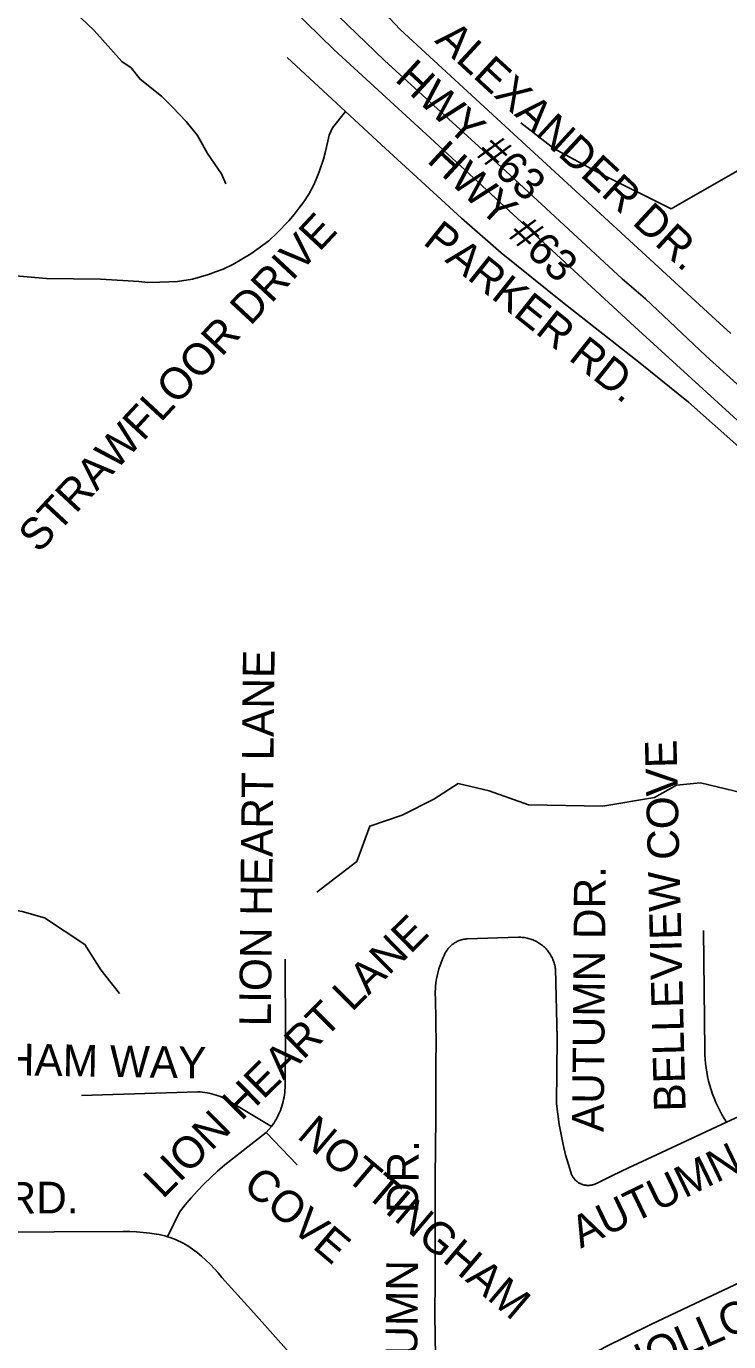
# Model space of a CAD drawing. Extents: x 1670563 to 1761545, y 515755 to 578944.
# Drawn here: x 1683746 to 1685409, y 542857 to 545971 of the extents above; entities that cross this region are included whole.
import ezdxf

# ---------------------------------------------------------------- set-up
doc = ezdxf.new("R2010")
doc.units = 0
for name, color, linetype in [('SHP_LINE', 7, 'Continuous'), ('STREETCL', 7, 'Continuous'), ('STRNAMES', 7, 'Continuous')]:
    doc.layers.add(name, color=color, linetype=linetype)

msp = doc.modelspace()

# ---------------------------------------------------------------- linework, layer by layer
at = {"layer": 'SHP_LINE'}
for points in [[(1683533, 546411), (1683633, 546396), (1683691, 546360), (1683739, 546315), (1683766, 546275), (1683782, 546206), (1683779, 546151), (1683794, 546106), (1683848, 546033), (1683875, 545991), (1683906, 545961), (1683972, 545888), (1683994, 545873), (1684015, 545846), (1684066, 545806), (1684093, 545779), (1684124, 545746), (1684151, 545713), (1684175, 545670), (1684208, 545622), (1684218, 545598)], [(1684917, 545743), (1684995, 545682), (1685100, 545625), (1685273, 545539)], [(1685799, 545725), (1685678, 545744), (1685563, 545715), (1685490, 545659), (1685431, 545630), (1685319, 545566), (1685273, 545539)], [(1684434, 543921), (1684528, 543994), (1684559, 544077), (1684636, 544103), (1684711, 544141), (1684768, 544178), (1684842, 544161), (1684935, 544128), (1685111, 544125), (1685233, 544145), (1685285, 544174), (1685342, 544180), (1685441, 544156), (1685585, 544093), (1685651, 544060), (1685728, 544033), (1685863, 544018), (1686108, 544018), (1686204, 544030), (1686304, 544039)], [(1683461, 543916), (1683562, 543899), (1683630, 543891), (1683686, 543884), (1683736, 543875), (1683789, 543860), (1683884, 543797), (1683922, 543737), (1683966, 543681)]]:
    msp.add_lwpolyline(points, dxfattribs=at)
at = {"layer": 'STREETCL'}
for points in [[(1685913, 544593.8), (1685635.2, 544850.4), (1685187, 545259.7), (1684701.8, 545707), (1684475, 545915.1), (1684373.9, 546014.5), (1684262.2, 546130.7), (1684078.4, 546335.4), (1683914.6, 546534.9), (1683762.8, 546737.1), (1683648.3, 546903.8)], [(1686352, 544277.5), (1686274.8, 544347.4), (1686127.6, 544481.9), (1685917.7, 544676.6), (1685823.7, 544763.5), (1685559.2, 545005.9), (1685354.8, 545191.1), (1685211.5, 545325.6), (1685156.9, 545373.2), (1684870.9, 545637.7), (1684593.7, 545890), (1684375.3, 546101.9), (1684267.7, 546222.4), (1684152.8, 546344.9), (1683979.8, 546552.3), (1683834.5, 546745.2), (1683737.6, 546884.7)], [(1685414.2, 545243.5), (1685368.8, 545285.1), (1684909.9, 545707.1), (1684630.7, 545963.6), (1684605.6, 545990.3), (1684588.3, 546012.2), (1684578.1, 546031.1), (1684563.2, 546061.6), (1684556.9, 546078.1), (1684551.4, 546095.4), (1684544.4, 546117.3), (1684543.6, 546126), (1684539.5, 546158.1), (1684540.3, 546197.3), (1684542.7, 546219.3), (1684557.6, 546314.2), (1684567, 546367.5), (1684572.8, 546409.2)], [(1684363.6, 545897.5), (1684501.9, 545769.4)], [(1683693.2, 545382.4), (1683793.4, 545374.4), (1683921.1, 545372.5), (1683974.4, 545369.6), (1684011.9, 545366.8), (1684033.7, 545364.6), (1684061.5, 545365.3), (1684103.4, 545366.8), (1684138.9, 545372.5), (1684177, 545383.3), (1684193.5, 545389.9), (1684211.8, 545396), (1684234.4, 545406.8), (1684277.7, 545432.2), (1684320, 545463.2), (1684339.7, 545482.4), (1684367, 545510.2), (1684379.7, 545525.7), (1684391.9, 545541.6), (1684402.7, 545555.3), (1684414.5, 545573.6), (1684426.7, 545595.7), (1684434.2, 545615), (1684439.4, 545626.7), (1684449.7, 545656.3), (1684454.4, 545674.6), (1684462.9, 545713.2), (1684470.5, 545731), (1684501.9, 545769.4)], [(1686398.1, 543856.6), (1686310.3, 543953.8), (1686281.8, 543991.3), (1686254.3, 544025.7), (1686213, 544084.8), (1686124.3, 544225.1), (1686098.4, 544260.6), (1686024.9, 544373.7), (1686016.9, 544386.4), (1685973.7, 544446.1), (1685936, 544493.1), (1685903.1, 544532.1), (1685835.1, 544604.4), (1685564.9, 544854.4), (1685433.2, 544975.2), (1685313.9, 545080.9), (1685199.2, 545173.5), (1685015.3, 545318.2), (1684870.5, 545435.2), (1684776, 545516.9), (1684718.3, 545570), (1684586.7, 545690.8), (1684501.9, 545769.4)], [(1685349.6, 543830.2), (1685352.1, 543547.6), (1685352.3, 543537), (1685353, 543526.3), (1685353.9, 543515.7), (1685355.3, 543505.1), (1685357, 543494.6), (1685359, 543484.2), (1685361.4, 543473.8), (1685364.1, 543463.5), (1685367.2, 543453.2), (1685370.6, 543443.1), (1685374.3, 543433.2), (1685378.4, 543423.3), (1685382.8, 543413.6), (1685387.5, 543404), (1685392.5, 543394.6), (1685397.9, 543385.4), (1685403.5, 543376.4)], [(1684715, 542820.5), (1684713.2, 542920), (1684713.7, 543002.6), (1684713.7, 543103.3), (1684713.9, 543202), (1684713.9, 543266.5), (1684714.5, 543294.7), (1684715.7, 543409.2), (1684715.7, 543521.9), (1684716.3, 543560), (1684714.4, 543671.1), (1684714.1, 543678), (1684714.1, 543684.9), (1684714.4, 543691.8), (1684714.9, 543698.6), (1684715.6, 543705.5), (1684716.5, 543712.3), (1684717.7, 543719.1), (1684719.1, 543725.9), (1684720.7, 543732.6), (1684722.6, 543739.2), (1684724.7, 543745.8), (1684727, 543752.2), (1684729.5, 543758.7), (1684732.3, 543765), (1684735.3, 543771.2), (1684736.1, 543773.2), (1684737, 543775.2), (1684737.9, 543777.1), (1684739, 543779), (1684740.1, 543780.8), (1684741.2, 543782.7), (1684742.4, 543784.4), (1684743.7, 543786.2), (1684745, 543787.9), (1684746.4, 543789.5), (1684747.9, 543791.1), (1684749.4, 543792.6), (1684751, 543794.1), (1684752.6, 543795.6), (1684754.2, 543796.9), (1684755.9, 543798.3), (1684757.7, 543799.5), (1684759.5, 543800.7), (1684761.3, 543801.9), (1684763.2, 543802.9), (1684765.1, 543803.9), (1684767, 543804.9), (1684769, 543805.7), (1684771, 543806.5), (1684773.1, 543807.3), (1684775.1, 543807.9), (1684777.2, 543808.5), (1684779.3, 543809), (1684781.4, 543809.5), (1684783.5, 543809.8), (1684785.7, 543810.1), (1684787.8, 543810.3), (1684789.9, 543810.5), (1684911, 543814.2), (1684913.9, 543814.2), (1684916.9, 543814.1), (1684919.8, 543814), (1684922.7, 543813.7), (1684925.7, 543813.4), (1684928.6, 543812.9), (1684931.4, 543812.3), (1684934.3, 543811.7), (1684937.1, 543810.9), (1684940, 543810), (1684942.7, 543809.1), (1684945.5, 543808), (1684948.2, 543806.9), (1684950.9, 543805.7), (1684953.5, 543804.3), (1684956.1, 543802.9), (1684958.6, 543801.4), (1684961.1, 543799.8), (1684963.5, 543798.2), (1684965.9, 543796.4), (1684968.2, 543794.6), (1684970.4, 543792.7), (1684972.6, 543790.7), (1684974.7, 543788.6), (1684976.7, 543786.5), (1684978.6, 543784.3), (1684980.5, 543782), (1684982.3, 543779.7), (1684984, 543777.3), (1684985.7, 543774.9), (1684987.2, 543772.4), (1684988.7, 543769.8), (1684990.1, 543767.2), (1684991.3, 543764.6), (1684992.5, 543761.9), (1684993.6, 543759.2), (1684994.6, 543756.4), (1684995.5, 543753.6), (1684996.4, 543750.8), (1684997.1, 543747.9), (1684997.7, 543745), (1684998.2, 543742.1), (1684998.6, 543739.2), (1685002.9, 543575.2), (1685001.1, 543419.7), (1685003.9, 543395.4), (1685007.5, 543371.2), (1685011.8, 543347.1), (1685017, 543323.2), (1685022.8, 543299.5), (1685029.5, 543275.9), (1685036.8, 543252.6), (1685037.4, 543251.3), (1685038, 543250), (1685038.7, 543248.7), (1685039.4, 543247.5), (1685040.2, 543246.3), (1685041, 543245.1), (1685041.8, 543243.9), (1685042.7, 543242.8), (1685043.6, 543241.7), (1685044.6, 543240.6), (1685045.5, 543239.5), (1685046.6, 543238.5), (1685047.6, 543237.6)], [(1684326, 543366.2), (1684329.2, 543370.7), (1684332.3, 543375.2), (1684335.2, 543379.8), (1684338, 543384.5), (1684340.6, 543389.4), (1684343, 543394.3), (1684345.3, 543399.3), (1684347.4, 543404.3), (1684349.3, 543409.4), (1684351, 543414.6), (1684352.6, 543419.9), (1684354, 543425.2), (1684355.1, 543430.5), (1684356.2, 543435.9), (1684357, 543441.3), (1684357.6, 543446.7), (1684358.1, 543452.2), (1684358.4, 543457.7), (1684359.6, 543578.1), (1684358.3, 543762.7)], [(1683876.6, 543439.3), (1684151.6, 543448.6), (1684157.1, 543448.2), (1684162.7, 543447.7), (1684168.1, 543447), (1684173.6, 543446.1), (1684179, 543445), (1684184.4, 543443.8), (1684189.8, 543442.3), (1684195.1, 543440.7), (1684200.3, 543438.9), (1684205.5, 543437), (1684210.6, 543434.9), (1684215.6, 543432.6), (1684326, 543366.2)], [(1685403.5, 543376.4), (1685463.6, 543404.3), (1685561.7, 543444.5), (1685569.6, 543447), (1685577.7, 543449.2), (1685585.8, 543451.2), (1685594, 543452.8), (1685602.2, 543454.2), (1685610.5, 543455.3), (1685618.8, 543456.2), (1685627.2, 543456.7), (1685635.5, 543457), (1685643.9, 543457)], [(1684313.4, 543351.7), (1684326, 543366.2)], [(1685047.6, 543237.6), (1685048.7, 543236.6), (1685049.9, 543235.7), (1685051.1, 543234.8), (1685052.3, 543233.9), (1685053.5, 543233.1), (1685054.8, 543232.4), (1685056.1, 543231.7), (1685057.4, 543231), (1685058.7, 543230.4), (1685060.1, 543229.8), (1685061.5, 543229.3), (1685062.9, 543228.8), (1685064.3, 543228.4), (1685065.7, 543228), (1685067.2, 543227.6), (1685068.6, 543227.4), (1685070.1, 543227.1), (1685071.6, 543226.9), (1685073, 543226.8), (1685074.5, 543226.7), (1685076, 543226.7), (1685077.5, 543226.7), (1685078.9, 543226.8), (1685080.4, 543226.9), (1685081.9, 543227.1), (1685083.3, 543227.3), (1685084.8, 543227.6), (1685086.2, 543227.9), (1685087.7, 543228.3), (1685089.1, 543228.7), (1685090.5, 543229.2), (1685091.9, 543229.7), (1685093.2, 543230.3), (1685094.6, 543230.9), (1685095.9, 543231.6), (1685133.4, 543250.2), (1685171.4, 543268), (1685237.7, 543299.3), (1685403.5, 543376.4)], [(1684080, 543105.2), (1684108.3, 543163), (1684122, 543180.5), (1684136.3, 543197.5), (1684151.1, 543214.1), (1684166.5, 543230.2), (1684182.4, 543245.7), (1684198.7, 543260.8), (1684215.6, 543275.2), (1684313.4, 543351.7)], [(1684387.4, 543275.5), (1684313.4, 543351.7)], [(1683647.9, 543116.2), (1683975.3, 543117.4), (1683991, 543117.2), (1684006.6, 543116.5), (1684022.3, 543115.2), (1684037.9, 543113.5), (1684053.4, 543111.3), (1684060.1, 543110.1), (1684066.8, 543108.7), (1684073.4, 543107), (1684080, 543105.2)], [(1684080, 543105.2), (1684086.3, 543103.1), (1684092.6, 543100.9), (1684098.8, 543098.5), (1684104.9, 543095.8), (1684110.9, 543093), (1684116.8, 543090), (1684122.7, 543086.8), (1684128.4, 543083.4), (1684134, 543079.8), (1684139.5, 543076), (1684144.8, 543072.1), (1684150, 543068), (1684160.7, 543059.1), (1684171, 543049.7), (1684180.9, 543040.1), (1684190.6, 543030.1), (1684199.8, 543019.7), (1684208.7, 543009), (1684284.1, 542924.8), (1684413.5, 542780.6)], [(1684715, 542778), (1684962.4, 542805.1), (1685030, 542814.2), (1685037.4, 542815.3), (1685044.7, 542816.7), (1685052, 542818.3), (1685059.2, 542820.1), (1685066.4, 542822.2), (1685073.5, 542824.4), (1685080.5, 542827), (1685087.5, 542829.7), (1685094.3, 542832.7), (1685101.1, 542835.9), (1685107.7, 542839.3), (1685114.2, 542842.9), (1685224.4, 542897.2), (1685329.3, 542947.2), (1685488.8, 543021.7), (1685516.9, 543035.2), (1685545.4, 543047.9), (1685574.2, 543059.9), (1685683, 543100.1)]]:
    msp.add_lwpolyline(points, dxfattribs=at)

# ---------------------------------------------------------------- texts
at = {"layer": 'STRNAMES'}
for s, rotation, p in [('ALEXANDER DR.', 317.3289, (1684710.7, 545935.2)), ('HWY #63', 317.3289, (1684616, 545843.6)), ('HWY #63', 317.3289, (1684691.9, 545651.2)), ('STRAWFLOOR DRIVE', 47.0666, (1683775.4, 544721.6)), ('PARKER RD.', 321.5099, (1684682.4, 545457.3)), ('LION HEART LANE', 89.4159, (1684324.7, 543602.9)), ('BELLEVIEW COVE', 91.4235, (1685307.1, 543402.3)), ('AUTUMN DR.', 89.5584, (1685112.9, 543352.9)), ('LION HEART LANE', 44.694, (1684068.8, 543192.9)), ('NOTTINGHAM WAY', 358.9984, (1683241, 543495.9)), ('NOTTINGHAM', 319.6498, (1684384.2, 543340.9)), ('AUTUMN DR.', 25.7791, (1685058.4, 543076.8)), ('AUTUMN    DR.', 89.5584, (1684669.9, 542620.5)), ('COVE', 319.6498, (1684255.1, 543220.6)), ('CASEY SPRINGS RD.', 0.2584, (1682849.8, 543156.1)), ('SPRING HOLLOW DR.', 23.8752, (1684787.9, 542590.6))]:
    msp.add_text(s, height=75, rotation=rotation, dxfattribs=at).set_placement(p)

doc.saveas('drawing.dxf')
